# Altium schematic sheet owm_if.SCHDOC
size A4; Organization: Microprocessor-Design Pty Ltd; Address1: 18/110 Caroline Street; Address2: South Yarra; Address3: VIC 3141; Address4: Australia; DocumentNumber: 3; SheetNumber: 3; SheetTotal: 3
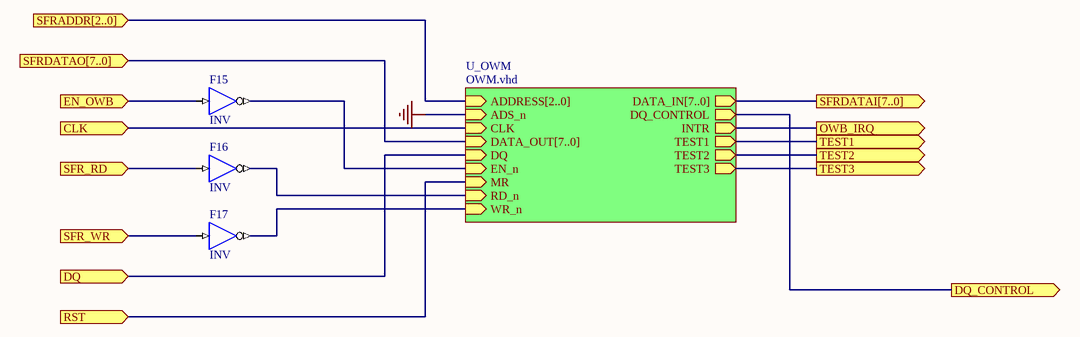
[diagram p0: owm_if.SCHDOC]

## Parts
F15  INV
F16  INV
F17  INV

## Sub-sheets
U_OWM = OWM.vhd: ADDRESS[2..0] (in), ADS_n (in), CLK (in), DATA_IN[7..0] (out), DATA_OUT[7..0] (in), DQ (in), DQ_CONTROL (out), EN_n (in), INTR (out), MR (in), RD_n (in), TEST1 (out), TEST2 (out), TEST3 (out), WR_n (in)  | VHDLENTITY: OWM

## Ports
CLK (in), DQ (in), DQ_CONTROL (out), EN_OWB (in), OWB_IRQ (out), RST (in), SFR_RD (in), SFR_WR (in), SFRADDR[2..0] (in), SFRDATAI[7..0] (out), SFRDATAO[7..0] (in), TEST1 (out), TEST2 (out), TEST3 (out)

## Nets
CLK: port CLK, sheet U_OWM/CLK
DQ: port DQ, sheet U_OWM/DQ
DQ_CONTROL: port DQ_CONTROL, sheet U_OWM/DQ_CONTROL
EN_OWB: F15.I ; port EN_OWB
OWB_IRQ: port OWB_IRQ, sheet U_OWM/INTR
RST: port RST, sheet U_OWM/MR
SFR_RD: F16.I ; port SFR_RD
SFR_WR: F17.I ; port SFR_WR
TEST1: port TEST1, sheet U_OWM/TEST1
TEST2: port TEST2, sheet U_OWM/TEST2
TEST3: port TEST3, sheet U_OWM/TEST3
NetF15_O: F15.O ; sheet U_OWM/EN_n
NetF16_O: F16.O ; sheet U_OWM/RD_n
NetF17_O: F17.O ; sheet U_OWM/WR_n

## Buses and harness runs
bus port SFRADDR[2..0] = sheet U_OWM/ADDRESS[2..0]
bus port SFRDATAI[7..0] = sheet U_OWM/DATA_IN[7..0]
bus port SFRDATAO[7..0] = sheet U_OWM/DATA_OUT[7..0]

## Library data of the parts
F15-F17 = INV: Inverter; ArchiveName: GENERIC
